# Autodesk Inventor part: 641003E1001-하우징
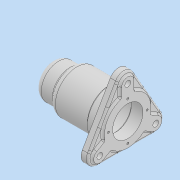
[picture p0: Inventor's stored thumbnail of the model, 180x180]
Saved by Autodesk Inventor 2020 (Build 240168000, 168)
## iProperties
Created: 2024-10
Part Number: 641003E1001-하우징
Material: 하우징
Document SubType Name: Modeling
Designer: oem
Density: 7.85 g/cm^3
Appearance: 기본값
Mass: 1860.35 g
Surface Area: 558.651 cm^2
Volume: 236.987 cm^3
Author: oem
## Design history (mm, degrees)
sketch "스케치1"
  geometry: C1 r 27 at (0, 0); 1 further point
  constraints: 1 centre point, 1 coincident
  dimensions: "d0" = 54 diameter of C1
extrude "돌출1" new body sketch "스케치1" distance "d1" = 29; taper "d2" = 0 deg
sketch "스케치2"
  geometry: C1 r 27 at (0, 0) reference; C2 r 33.5 at (0, 0)
  constraints: 1 centre point, 1 coincident
  dimensions: "d3" = 67 diameter of C2
extrude "돌출2" join sketch "스케치2" distance "d4" = 62; taper "d5" = 0 deg
sketch "스케치3"
  geometry: C1 r 33.5 at (0, 0) reference; C2 r 36.5 at (0, 0)
  constraints: 1 centre point, 1 coincident
  dimensions: "d6" = 73 diameter of C2
extrude "돌출3" join sketch "스케치3" distance "d7" = 12; taper "d8" = 0 deg
sketch "스케치4" dims "d9" = 100
  geometry: L1 (-12.99, 57.5)-(-56.292, -17.5); L2 (12.99, 57.5)-(56.292, -17.5); L3 (-43.301, -40)-(43.301, -40); C1 r 36.5 at (0, 0) reference; A1 r 15 centre (0, 50) between (-12.99, 57.5) and (12.99, 57.5); A2 r 15 centre (-43.301, -25) between (-43.301, -40) and (-56.292, -17.5); A3 r 15 centre (43.301, -25) between (43.301, -40) and (56.292, -17.5); 1 further point
  constraints: 6 end point, 6 point on circle, 5 tangent, 3 centre point, 2 vertical alignment, 1 coincident, 1 horizontal, 9 other
  dimensions: "d10" = 30 diameter of A1; "d13" = 360 deg dimension on C1.centre A1.centre (derived)
extrude "돌출4" join sketch "스케치4" distance "d15" = 11; taper "d16" = 0 deg
sketch "스케치5"
  geometry: L1 (-9.5, 50)-(-9.5, 34.724); L2 (9.5, 50)-(9.5, 34.724); L3 (-38.551, -33.227)-(-25.322, -25.589); L4 (-48.051, -16.773)-(-34.822, -9.135); L5 (48.051, -16.773)-(34.822, -9.135); L6 (38.551, -33.227)-(25.322, -25.589); A1 r 15 centre (0, 50) between (12.99, 57.5) and (-12.99, 57.5) reference; A2 r 9.5 centre (0, 50) between (9.5, 50) and (-9.5, 50); A3 r 9.5 centre (-43.301, -25) between (-48.051, -16.773) and (-38.551, -33.227); A4 r 9.5 centre (43.301, -25) between (38.551, -33.227) and (48.051, -16.773); A5 r 36 centre (0, 0) between (-9.5, 34.724) and (-34.822, -9.135); A6 r 36 centre (0, 0) between (-25.322, -25.589) and (25.322, -25.589); A7 r 36 centre (0, 0) between (34.822, -9.135) and (9.5, 34.724); 1 further point
  constraints: 12 end point, 12 point on circle, 6 centre point, 2 tangent, 2 vertical, 1 coincident, 1 concentric, 25 other
  dimensions: "d17" = 19 diameter of A2; "d21" = 360 deg dimension on point (0, 0) A2.centre (derived); "d23" = 36 radius of A7
extrude "돌출5" join sketch "스케치5" distance "d24" = 3; taper "d25" = 0 deg
sketch "스케치6"
  geometry: A1 r 9.5 centre (0, 50) between (9.5, 50) and (-9.5, 50) reference; A2 r 9.5 centre (-43.301, -25) between (-48.051, -16.773) and (-38.551, -33.227) reference; A3 r 9.5 centre (43.301, -25) between (38.551, -33.227) and (48.051, -16.773) reference
hole "구멍1" sketch "스케치6" at (0, 50), (43.301, -25), (-43.301, -25) diameter "d26" = 9; stored, may be unused: countersink angle "d30" = 90 deg, drill point angle "d32" = 118 deg; dims "d27" = 8, "d28" = 4, "d29" = 2, "d31" = 8
sketch "스케치7"
  geometry: C1 r 23.5 at (0, 0); A1 r 36 centre (0, 0) between (-25.322, -25.589) and (25.322, -25.589) reference
  constraints: 1 centre point, 1 coincident
  dimensions: "d33" = 47 diameter of C1
extrude "돌출6" cut sketch "스케치7" distance "d34" = 18; taper "d35" = 0 deg
sketch "스케치8"
  geometry: C1 r 23.5 at (0, 0) reference; C2 r 26.5 at (0, 0)
  constraints: 1 centre point, 1 coincident
  dimensions: "d36" = 53 diameter of C2
extrude "돌출7" cut sketch "스케치8" distance "d37" = 48; taper "d38" = 0 deg
sketch "스케치9"
  geometry: C1 r 26.5 at (0, 0) reference; C2 r 23.5 at (0, 0)
  constraints: 1 centre point, 1 coincident
  dimensions: "d39" = 47 diameter of C2
extrude "돌출8" cut sketch "스케치9" distance "d40" = 14; taper "d41" = 0 deg
sketch "스케치10"
  geometry: C1 r 23.5 at (0, 0) reference; C2 r 21 at (0, 0)
  constraints: 1 centre point, 1 coincident
  dimensions: "d42" = 42 diameter of C2
extrude "돌출9" cut sketch "스케치10" distance "d43" = 18; taper "d44" = 0 deg
sketch "스케치11"
  geometry: C1 r 21 at (0, 0) reference; C2 r 17.5 at (0, 0)
  constraints: 1 centre point, 1 coincident
  dimensions: "d45" = 35 diameter of C2
extrude "돌출10" cut sketch "스케치11" distance "d46" = 4; taper "d47" = 0 deg
sketch "스케치12"
  geometry: C1 r 17.5 at (0, 0) reference; C2 r 12 at (0, 0)
  constraints: 1 centre point, 1 coincident
  dimensions: "d48" = 24 diameter of C2
extrude "돌출11" cut sketch "스케치12" distance "d49" = 5; taper "d50" = 0 deg
fillet "모깎기1" dims "d54" = 3
fillet "모깎기2" dims "d55" = 1
fillet "모깎기3" dims "d56" = 3
fillet "모깎기4" dims "d57" = 1
fillet "모깎기5" dims "d58" = 10
fillet "모깎기6" dims "d59" = 3
fillet "모깎기7" dims "d60" = 3
fillet "모깎기8" dims "d61" = 3
fillet "모깎기9" dims "d62" = 3
sketch "스케치13"
  geometry: C1 r 23.5 at (0, 0) reference; 1 further point
  constraints: 1 vertical alignment
  dimensions: "d63" = 30 distance of C1.centre point (0, 30)
hole "구멍2" sketch "스케치13" at (0, 30) diameter "d64" = 3.242; stored, may be unused: countersink angle "d68" = 90 deg, drill point angle "d70" = 118 deg; dims "d65" = 10, "d66" = 4, "d67" = 2, "d69" = 12
node "솔리드1"
pattern_circular "원형 패턴1" dims angle "d72" = 360 deg
feature "A9D066F2-1C7D-4E18-AEED-F7BC21143FA4" dims "d26" = 9, "d27" = 8, "d28" = 4, "d29" = 2, "d30" = 90 deg, "d31" = 8, "d32" = 118 deg
other parameters: "d18" = 72
